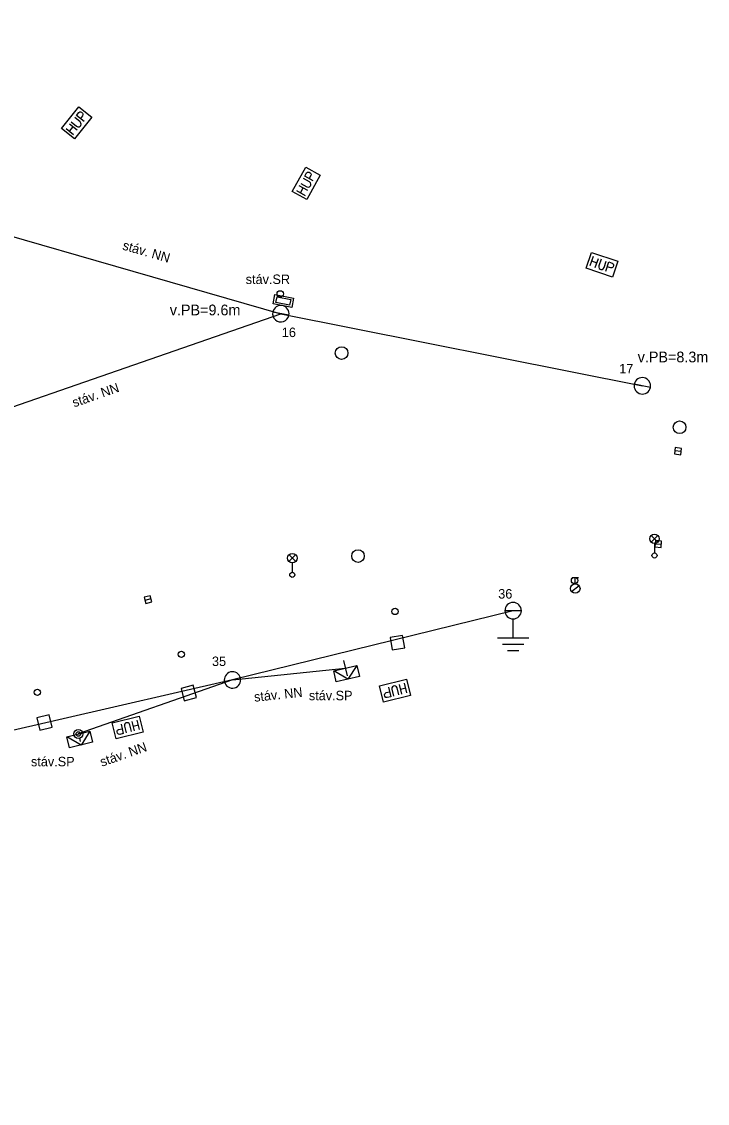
# Model space of a CAD drawing. Extents: x -544660 to -541587, y -1198996 to -1195866.
# Drawn here: x -542945.2 to -542890.9, y -1198225.6 to -1198140 of the extents above; entities that cross this region are included whole.
import ezdxf

# ---------------------------------------------------------------- set-up
doc = ezdxf.new("R2010")
doc.units = 0
for name, color, linetype in [('CIZÍ_NADZEM', 7, 'Continuous'), ('DOPLŇ_POPISY', 7, 'Continuous'), ('ELE_EON', 7, 'Continuous'), ('ELE_EON_POPIS', 7, 'Continuous')]:
    doc.layers.add(name, color=color, linetype=linetype)

msp = doc.modelspace()

# ---------------------------------------------------------------- linework, layer by layer
at = {"layer": 'CIZÍ_NADZEM'}
for p, q in [((-542892.972, -1198174.042), (-542893.468, -1198173.978)), ((-542895.344, -1198181.208), (-542894.816, -1198180.68)), ((-542894.808, -1198181.205), (-542895.336, -1198180.676)), ((-542895.08, -1198181.32), (-542895.08, -1198182.07)), ((-542895.029, -1198181.343), (-542894.531, -1198181.377)), ((-542924.014, -1198182.738), (-542923.486, -1198182.21)), ((-542923.478, -1198182.735), (-542924.006, -1198182.206)), ((-542923.75, -1198182.85), (-542923.75, -1198183.6)), ((-542901.6, -1198184.015), (-542901.1, -1198184.015)), ((-542901.35, -1198184.515), (-542901.35, -1198184.015)), ((-542901.644, -1198185.121), (-542901.054, -1198184.658)), ((-542934.938, -1198185.696), (-542935.422, -1198185.824)), ((-542915.024, -1198188.591), (-542916.009, -1198188.764)), ((-542916.009, -1198188.764), (-542915.836, -1198189.749)), ((-542914.851, -1198189.576), (-542915.024, -1198188.591)), ((-542915.836, -1198189.749), (-542914.851, -1198189.576)), ((-542931.595, -1198192.548), (-542932.562, -1198192.805)), ((-542932.562, -1198192.805), (-542932.305, -1198193.772)), ((-542931.338, -1198193.515), (-542931.595, -1198192.548)), ((-542932.305, -1198193.772), (-542931.338, -1198193.515)), ((-542943.004, -1198194.895), (-542943.975, -1198195.134)), ((-542942.765, -1198195.866), (-542943.004, -1198194.895)), ((-542943.975, -1198195.134), (-542943.736, -1198196.105)), ((-542943.736, -1198196.105), (-542942.765, -1198195.866))]:
    msp.add_line(p, q, dxfattribs=at)
for points in [[(-542942.018, -1198148.463), (-542940.642, -1198146.746), (-542939.612, -1198147.572), (-542940.988, -1198149.288), (-542942.018, -1198148.463)], [(-542941.253, -1198147.948), (-542940.822, -1198148.293), (-542940.719, -1198148.337), (-542940.619, -1198148.329), (-542940.532, -1198148.28), (-542940.493, -1198148.231), (-542940.463, -1198148.135), (-542940.481, -1198148.04), (-542940.546, -1198147.948), (-542940.977, -1198147.603)], [(-542940.84, -1198147.433), (-542940.662, -1198147.21), (-542940.575, -1198147.161), (-542940.526, -1198147.158), (-542940.451, -1198147.179), (-542940.365, -1198147.248), (-542940.327, -1198147.318), (-542940.321, -1198147.365), (-542940.349, -1198147.46), (-542940.528, -1198147.683)], [(-542940.239, -1198147.915), (-542940.84, -1198147.433)], [(-542941.666, -1198148.463), (-542941.065, -1198148.945)], [(-542940.788, -1198148.6), (-542941.389, -1198148.118)], [(-542941.382, -1198148.69), (-542941.106, -1198148.345)], [(-542923.759, -1198153.446), (-542922.685, -1198151.526), (-542921.533, -1198152.17), (-542922.607, -1198154.09), (-542923.759, -1198153.446)], [(-542922.767, -1198152.236), (-542922.628, -1198151.986), (-542922.551, -1198151.924), (-542922.503, -1198151.913), (-542922.425, -1198151.921), (-542922.329, -1198151.975), (-542922.281, -1198152.037), (-542922.266, -1198152.083), (-542922.279, -1198152.182), (-542922.418, -1198152.431)], [(-542923.089, -1198152.812), (-542922.608, -1198153.081), (-542922.498, -1198153.107), (-542922.401, -1198153.083), (-542922.324, -1198153.02), (-542922.293, -1198152.965), (-542922.28, -1198152.866), (-542922.313, -1198152.775), (-542922.392, -1198152.696), (-542922.874, -1198152.426)], [(-542922.095, -1198152.612), (-542922.767, -1198152.236)], [(-542923.412, -1198153.388), (-542922.739, -1198153.764)], [(-542922.524, -1198153.378), (-542923.196, -1198153.002)], [(-542923.095, -1198153.565), (-542922.879, -1198153.179)], [(-542900.059, -1198158.277), (-542897.975, -1198158.982), (-542898.398, -1198160.233), (-542900.482, -1198159.527), (-542900.059, -1198158.277)], [(-542899.939, -1198158.608), (-542900.185, -1198159.337)], [(-542899.767, -1198159.479), (-542899.52, -1198158.75)], [(-542899.313, -1198158.82), (-542899.49, -1198159.342), (-542899.496, -1198159.455), (-542899.455, -1198159.546), (-542899.378, -1198159.611), (-542899.319, -1198159.631), (-542899.219, -1198159.625), (-542899.136, -1198159.577), (-542899.072, -1198159.484), (-542898.895, -1198158.961)], [(-542900.055, -1198158.952), (-542899.636, -1198159.094)], [(-542898.935, -1198159.761), (-542898.688, -1198159.031)], [(-542898.688, -1198159.031), (-542898.417, -1198159.123), (-542898.342, -1198159.187), (-542898.322, -1198159.232), (-542898.316, -1198159.31), (-542898.351, -1198159.414), (-542898.404, -1198159.474), (-542898.447, -1198159.496), (-542898.546, -1198159.502), (-542898.816, -1198159.41)], [(-542914.399, -1198193.352), (-542916.536, -1198193.873), (-542916.849, -1198192.591), (-542914.711, -1198192.069), (-542914.399, -1198193.352)], [(-542915.96, -1198193.449), (-542916.238, -1198193.517), (-542916.336, -1198193.503), (-542916.377, -1198193.476), (-542916.424, -1198193.413), (-542916.45, -1198193.306), (-542916.437, -1198193.228), (-542916.413, -1198193.186), (-542916.333, -1198193.129), (-542916.055, -1198193.061)], [(-542916.142, -1198192.701), (-542915.96, -1198193.449)], [(-542915.319, -1198193.293), (-542915.449, -1198192.757), (-542915.505, -1198192.659), (-542915.589, -1198192.604), (-542915.688, -1198192.591), (-542915.749, -1198192.605), (-542915.83, -1198192.663), (-542915.874, -1198192.749), (-542915.879, -1198192.862), (-542915.748, -1198193.398)], [(-542915.289, -1198192.493), (-542915.107, -1198193.242)], [(-542914.763, -1198192.784), (-542915.193, -1198192.889)], [(-542914.678, -1198193.137), (-542914.86, -1198192.389)], [(-542935.567, -1198196.269), (-542937.703, -1198196.794), (-542938.018, -1198195.513), (-542935.882, -1198194.987), (-542935.567, -1198196.269)], [(-542937.312, -1198195.622), (-542937.128, -1198196.37)], [(-542936.487, -1198196.212), (-542936.619, -1198195.676), (-542936.675, -1198195.579), (-542936.758, -1198195.524), (-542936.857, -1198195.51), (-542936.918, -1198195.525), (-542937, -1198195.584), (-542937.044, -1198195.669), (-542937.048, -1198195.782), (-542936.916, -1198196.318)], [(-542936.459, -1198195.412), (-542936.275, -1198196.16)], [(-542935.933, -1198195.702), (-542936.362, -1198195.808)], [(-542935.846, -1198196.055), (-542936.03, -1198195.307)], [(-542937.128, -1198196.37), (-542937.406, -1198196.438), (-542937.504, -1198196.424), (-542937.544, -1198196.397), (-542937.592, -1198196.335), (-542937.618, -1198196.228), (-542937.605, -1198196.149), (-542937.582, -1198196.108), (-542937.501, -1198196.05), (-542937.223, -1198195.981)]]:
    msp.add_lwpolyline(points, dxfattribs=at)
for points in [[(-542892.94, -1198173.793), (-542893.436, -1198173.729), (-542893.501, -1198174.226), (-542893.004, -1198174.29)], [(-542895.047, -1198181.593), (-542894.547, -1198181.627), (-542894.513, -1198181.127), (-542895.012, -1198181.093)], [(-542935.003, -1198185.453), (-542935.487, -1198185.582), (-542935.358, -1198186.066), (-542934.874, -1198185.938)]]:
    msp.add_lwpolyline(points, close=True, dxfattribs=at)
for centre, radius in [((-542924.71, -1198161.56), 0.25), ((-542919.85, -1198166.25), 0.5), ((-542893.09, -1198172.12), 0.5), ((-542895.08, -1198180.945), 0.375), ((-542918.55, -1198182.32), 0.5), ((-542923.75, -1198182.475), 0.375), ((-542895.08, -1198182.27), 0.2), ((-542923.75, -1198183.8), 0.2), ((-542901.35, -1198184.89), 0.375), ((-542901.41, -1198184.25), 0.25), ((-542915.62, -1198186.7), 0.25), ((-542932.53, -1198190.09), 0.25), ((-542943.93, -1198193.1), 0.25)]:
    msp.add_circle(centre, radius, dxfattribs=at)
at = {"layer": 'ELE_EON'}
for p, q in [((-542924.023, -1198163.257), (-542925.297, -1198163.003)), ((-542895.403, -1198168.97), (-542896.677, -1198168.71)), ((-542905.62, -1198186.64), (-542906.92, -1198186.64)), ((-542906.27, -1198188.79), (-542906.27, -1198187.29)), ((-542907.52, -1198188.79), (-542905.02, -1198188.79)), ((-542907.12, -1198189.29), (-542905.42, -1198189.29)), ((-542919.701, -1198190.581), (-542919.419, -1198191.799)), ((-542906.72, -1198189.79), (-542905.82, -1198189.79)), ((-542927.859, -1198191.964), (-542929.121, -1198192.276)), ((-542940.606, -1198196.74), (-542940.546, -1198196.982))]:
    msp.add_line(p, q, dxfattribs=at)
for points in [[(-542988.53, -1198140.01), (-542959.64, -1198153.06), (-542924.66, -1198163.13), (-542896.04, -1198168.84)], [(-542975.57, -1198180.94), (-542961.5, -1198175.92), (-542924.66, -1198163.13)], [(-542906.27, -1198186.64), (-542928.49, -1198192.12), (-542956, -1198198.44), (-542981.94, -1198206.13), (-543006.12, -1198212.41), (-543012.46, -1198213.75), (-543024.08, -1198216.65), (-543037.78, -1198219.79), (-543046.51, -1198221.61), (-543057.18, -1198224.62), (-543064.71, -1198225.64)], [(-542928.49, -1198192.12), (-542919.56, -1198191.19)], [(-542918.647, -1198190.979), (-542919.357, -1198192.067), (-542920.473, -1198191.401)], [(-542928.49, -1198192.12), (-542940.69, -1198196.4)], [(-542939.78, -1198196.176), (-542940.475, -1198197.274), (-542941.6, -1198196.624)]]:
    msp.add_lwpolyline(points, dxfattribs=at)
for points in [[(-542925.122, -1198161.61), (-542923.651, -1198161.904), (-542923.797, -1198162.639), (-542925.268, -1198162.346)], [(-542924.955, -1198161.797), (-542923.876, -1198162.012), (-542923.964, -1198162.453), (-542925.043, -1198162.238)], [(-542918.444, -1198191.856), (-542920.271, -1198192.278), (-542920.473, -1198191.401), (-542918.647, -1198190.979)], [(-542939.565, -1198197.05), (-542941.386, -1198197.498), (-542941.6, -1198196.624), (-542939.78, -1198196.176)]]:
    msp.add_lwpolyline(points, close=True, dxfattribs=at)
for radius in [0.35, 0.175]:
    msp.add_circle((-542940.69, -1198196.4), radius, dxfattribs=at)
for centre, start, end in [((-542924.66, -1198163.13), 168.71702, 348.71702), ((-542924.66, -1198163.13), 348.71702, 168.71702), ((-542896.04, -1198168.84), 348.44719, 168.44719), ((-542896.04, -1198168.84), 168.44719, 348.44719), ((-542906.27, -1198186.64), 0, 180), ((-542906.27, -1198186.64), 180, 0), ((-542928.49, -1198192.12), 13.85408, 193.85408), ((-542928.49, -1198192.12), 193.85408, 13.85408)]:
    msp.add_arc(centre, 0.65, start, end, dxfattribs=at)

# ---------------------------------------------------------------- texts
at = {"layer": 'DOPLŇ_POPISY'}
for s, p in [('v.PB=9.6m', (-542933.45, -1198163.26)), ('v.PB=8.3m', (-542896.41, -1198166.98))]:
    msp.add_text(s, height=0.85, dxfattribs=at).set_placement(p)
at = {"layer": 'ELE_EON_POPIS'}
for rotation, p in [(343.94001, (-542937.25, -1198158.04)), (19.14582, (-542941.02, -1198170.55)), (5.94554, (-542926.74, -1198193.85)), (19.33187, (-542938.82, -1198199))]:
    msp.add_text('stáv. NN', height=0.75, rotation=rotation, dxfattribs=at).set_placement(p)
for s, p in [('stáv.SR', (-542927.44, -1198160.78)), ('16', (-542924.58, -1198164.98)), ('17', (-542897.87, -1198167.85)), ('36', (-542907.45, -1198185.68)), ('35', (-542930.11, -1198191.02)), ('stáv.SP', (-542922.44, -1198193.73)), ('stáv.SP', (-542944.44, -1198198.96))]:
    msp.add_text(s, height=0.75, dxfattribs=at).set_placement(p)

doc.saveas('drawing.dxf')
